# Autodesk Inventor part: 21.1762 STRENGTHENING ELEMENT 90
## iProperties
Company: MiniTec Framing Systems, LLC
Created: 2007-04
Part Number: 21.1762 STRENGTHENING ELEMENT 90
Material: Aluminum-6061
Document SubType Name: Modeling
Designer: Andy Moles
Density: 2.71 g/cm^3
Author: Andy Moles
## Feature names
1. Extrusion1
2. Extrusion2
3. Extrusion3
4. Extrusion4
5. Mirror1
